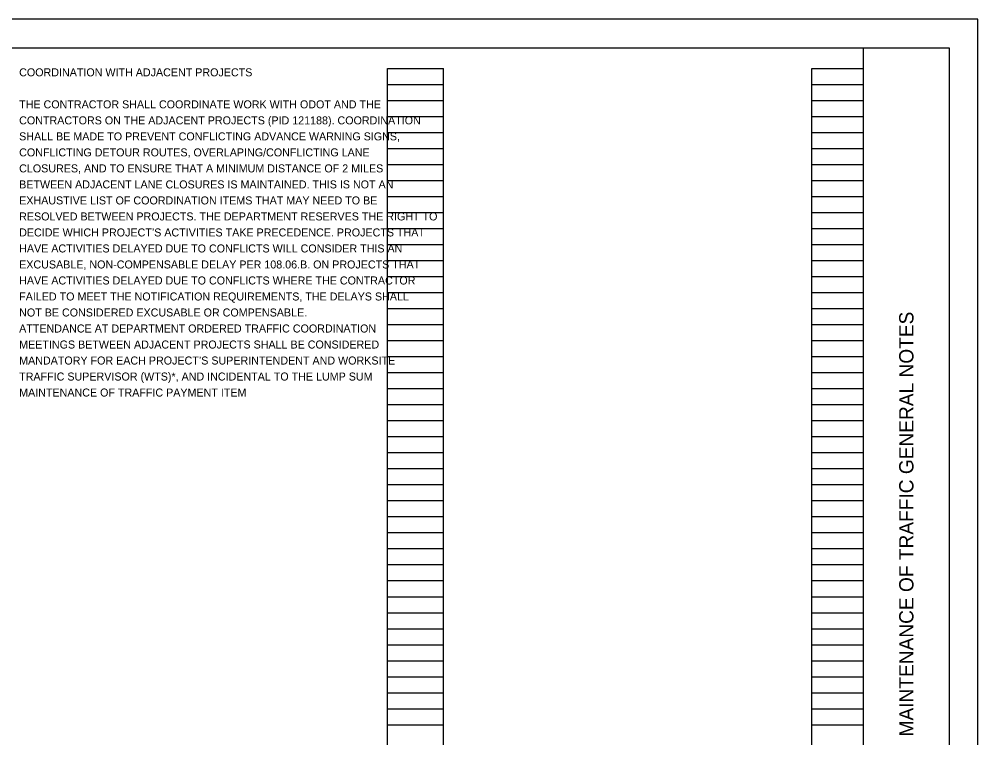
# Model space of a CAD drawing. Extents: x 0 to 34, y 0 to 22.
# Drawn here: x 17.24 to 34, y 9.43 to 22 of the extents above; entities that cross this region are included whole.
import ezdxf

# ---------------------------------------------------------------- set-up
doc = ezdxf.new("R2010")
doc.units = 0
for name, color, linetype in [('SH_Border', 7, 'Continuous'), ('SH_Cut_Line', 7, 'Continuous'), ('SH_Data', 7, 'Continuous'), ('SH_Text', 7, 'Continuous')]:
    doc.layers.add(name, color=color, linetype=linetype)

msp = doc.modelspace()

# ---------------------------------------------------------------- linework, layer by layer
at = {"layer": 'SH_Border'}
msp.add_line((32, 0.5), (32, 21.5), dxfattribs=at)
msp.add_lwpolyline([(1.5, 21.5), (33.5, 21.5), (33.5, 0.5), (1.5, 0.5)], close=True, dxfattribs=at)
at = {"layer": 'SH_Cut_Line'}
msp.add_lwpolyline([(0, 0), (34, 0), (34, 22), (0, 22)], close=True, dxfattribs=at)
at = {"layer": 'SH_Data'}
for p, q in [((23.68, 0.98), (23.68, 21.14)), ((23.68, 21.14), (24.66, 21.14)), ((24.66, 0.98), (24.66, 21.14)), ((31.1, 0.98), (31.1, 21.14)), ((31.1, 21.14), (32, 21.14)), ((32, 0.98), (32, 21.14)), ((23.68, 20.86), (24.66, 20.86)), ((31.1, 20.86), (32, 20.86)), ((23.68, 20.58), (24.66, 20.58)), ((31.1, 20.58), (32, 20.58)), ((23.68, 20.3), (24.66, 20.3)), ((31.1, 20.3), (32, 20.3)), ((23.68, 20.02), (24.66, 20.02)), ((31.1, 20.02), (32, 20.02)), ((23.68, 19.74), (24.66, 19.74)), ((31.1, 19.74), (32, 19.74)), ((23.68, 19.46), (24.66, 19.46)), ((31.1, 19.46), (32, 19.46)), ((23.68, 19.18), (24.66, 19.18)), ((31.1, 19.18), (32, 19.18)), ((23.68, 18.9), (24.66, 18.9)), ((31.1, 18.9), (32, 18.9)), ((23.68, 18.62), (24.66, 18.62)), ((31.1, 18.62), (32, 18.62)), ((23.68, 18.34), (24.66, 18.34)), ((31.1, 18.34), (32, 18.34)), ((23.68, 18.06), (24.66, 18.06)), ((31.1, 18.06), (32, 18.06)), ((23.68, 17.78), (24.66, 17.78)), ((31.1, 17.78), (32, 17.78)), ((23.68, 17.5), (24.66, 17.5)), ((31.1, 17.5), (32, 17.5)), ((23.68, 17.22), (24.66, 17.22)), ((31.1, 17.22), (32, 17.22)), ((23.68, 16.94), (24.66, 16.94)), ((31.1, 16.94), (32, 16.94)), ((23.68, 16.66), (24.66, 16.66)), ((31.1, 16.66), (32, 16.66)), ((23.68, 16.38), (24.66, 16.38)), ((31.1, 16.38), (32, 16.38)), ((23.68, 16.1), (24.66, 16.1)), ((31.1, 16.1), (32, 16.1)), ((23.68, 15.82), (24.66, 15.82)), ((31.1, 15.82), (32, 15.82)), ((23.68, 15.54), (24.66, 15.54)), ((31.1, 15.54), (32, 15.54)), ((23.68, 15.26), (24.66, 15.26)), ((31.1, 15.26), (32, 15.26)), ((23.68, 14.98), (24.66, 14.98)), ((31.1, 14.98), (32, 14.98)), ((23.68, 14.7), (24.66, 14.7)), ((31.1, 14.7), (32, 14.7)), ((23.68, 14.42), (24.66, 14.42)), ((31.1, 14.42), (32, 14.42)), ((23.68, 14.14), (24.66, 14.14)), ((31.1, 14.14), (32, 14.14)), ((23.68, 13.86), (24.66, 13.86)), ((31.1, 13.86), (32, 13.86)), ((23.68, 13.58), (24.66, 13.58)), ((31.1, 13.58), (32, 13.58)), ((23.68, 13.3), (24.66, 13.3)), ((31.1, 13.3), (32, 13.3)), ((23.68, 13.02), (24.66, 13.02)), ((31.1, 13.02), (32, 13.02)), ((23.68, 12.74), (24.66, 12.74)), ((31.1, 12.74), (32, 12.74)), ((23.68, 12.46), (24.66, 12.46)), ((31.1, 12.46), (32, 12.46)), ((23.68, 12.18), (24.66, 12.18)), ((31.1, 12.18), (32, 12.18)), ((23.68, 11.9), (24.66, 11.9)), ((31.1, 11.9), (32, 11.9)), ((23.68, 11.62), (24.66, 11.62)), ((31.1, 11.62), (32, 11.62)), ((23.68, 11.34), (24.66, 11.34)), ((31.1, 11.34), (32, 11.34)), ((23.68, 11.06), (24.66, 11.06)), ((31.1, 11.06), (32, 11.06)), ((23.68, 10.78), (24.66, 10.78)), ((31.1, 10.78), (32, 10.78)), ((23.68, 10.5), (24.66, 10.5)), ((31.1, 10.5), (32, 10.5)), ((23.68, 10.22), (24.66, 10.22)), ((31.1, 10.22), (32, 10.22)), ((23.68, 9.94), (24.66, 9.94)), ((31.1, 9.94), (32, 9.94)), ((23.68, 9.66), (24.66, 9.66)), ((31.1, 9.66), (32, 9.66))]:
    msp.add_line(p, q, dxfattribs=at)

# ---------------------------------------------------------------- texts
msp.add_text('MAINTENANCE OF TRAFFIC GENERAL NOTES', height=0.25, rotation=90, dxfattribs=at).set_placement((32.875, 9.455))
at = {"layer": 'SH_Text'}
for s, p in [('COORDINATION WITH ADJACENT PROJECTS', (17.24, 21)), ('THE CONTRACTOR SHALL COORDINATE WORK WITH ODOT AND THE', (17.24, 20.44)), ('CONTRACTORS ON THE ADJACENT PROJECTS (PID 121188). COORDINATION', (17.24, 20.16)), ('SHALL BE MADE TO PREVENT CONFLICTING ADVANCE WARNING SIGNS,', (17.24, 19.88)), ('CONFLICTING DETOUR ROUTES, OVERLAPING/CONFLICTING LANE', (17.24, 19.6)), ('CLOSURES, AND TO ENSURE THAT A MINIMUM DISTANCE OF 2 MILES', (17.24, 19.32)), ('BETWEEN ADJACENT LANE CLOSURES IS MAINTAINED. THIS IS NOT AN', (17.24, 19.04)), ('EXHAUSTIVE LIST OF COORDINATION ITEMS THAT MAY NEED TO BE', (17.24, 18.76)), ('RESOLVED BETWEEN PROJECTS. THE DEPARTMENT RESERVES THE RIGHT TO', (17.24, 18.48)), ('DECIDE WHICH PROJECT’S ACTIVITIES TAKE PRECEDENCE. PROJECTS THAT', (17.24, 18.2)), ('HAVE ACTIVITIES DELAYED DUE TO CONFLICTS WILL CONSIDER THIS AN', (17.24, 17.92)), ('EXCUSABLE, NON-COMPENSABLE DELAY PER 108.06.B. ON PROJECTS THAT', (17.24, 17.64)), ('HAVE ACTIVITIES DELAYED DUE TO CONFLICTS WHERE THE CONTRACTOR', (17.24, 17.36)), ('FAILED TO MEET THE NOTIFICATION REQUIREMENTS, THE DELAYS SHALL', (17.24, 17.08)), ('NOT BE CONSIDERED EXCUSABLE OR COMPENSABLE.', (17.24, 16.8)), ('ATTENDANCE AT DEPARTMENT ORDERED TRAFFIC COORDINATION', (17.24, 16.52)), ('MEETINGS BETWEEN ADJACENT PROJECTS SHALL BE CONSIDERED', (17.24, 16.24)), ('MANDATORY FOR EACH PROJECT’S SUPERINTENDENT AND WORKSITE', (17.24, 15.96)), ('TRAFFIC SUPERVISOR (WTS)*, AND INCIDENTAL TO THE LUMP SUM', (17.24, 15.68)), ('MAINTENANCE OF TRAFFIC PAYMENT ITEM', (17.24, 15.4))]:
    msp.add_text(s, height=0.14, dxfattribs=at).set_placement(p)

doc.saveas('drawing.dxf')
